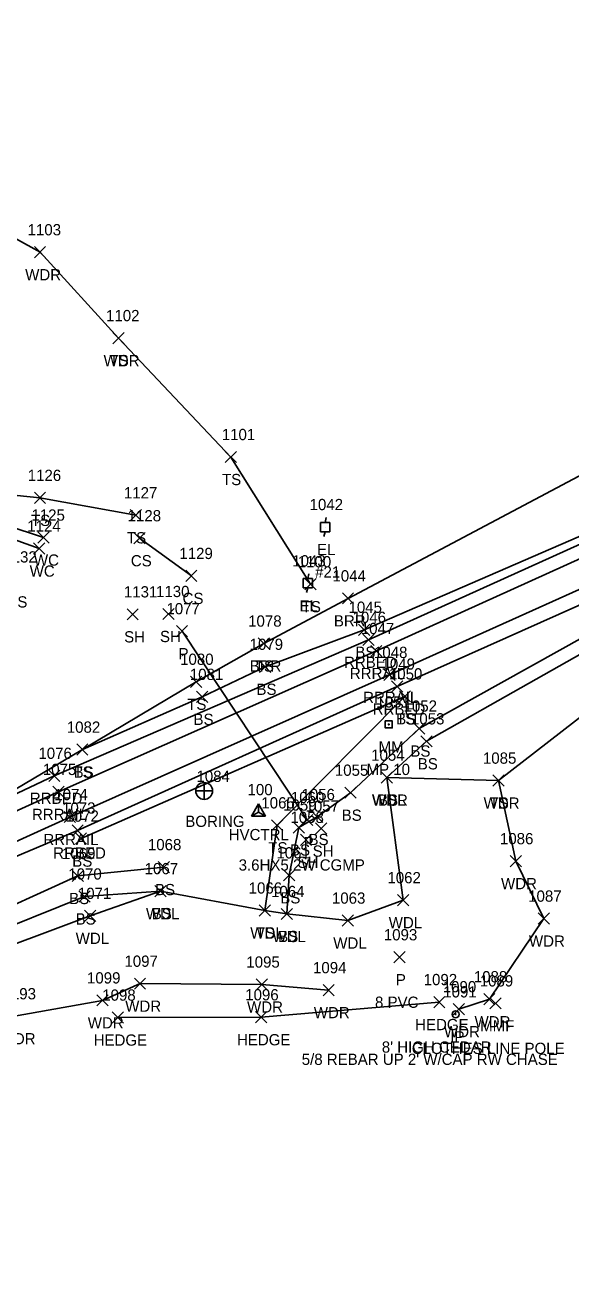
# Model space of a CAD drawing. Extents: x 1640777 to 1641692, y 610911 to 611377.
# Drawn here: x 1641419.5 to 1641516.6, y 611149.3 to 611372 of the extents above; entities that cross this region are included whole.
import ezdxf

# ---------------------------------------------------------------- set-up
doc = ezdxf.new("R2010")
doc.units = 0
for name, color, linetype in [('C_A', 7, 'Continuous'), ('C_I', 7, 'Continuous'), ('CPSM', 7, 'Continuous'), ('D_A', 7, 'Continuous'), ('D_C', 7, 'Continuous'), ('D_I', 7, 'Continuous'), ('D_TIC', 7, 'Continuous'), ('DCP', 7, 'Continuous'), ('G_A', 7, 'Continuous'), ('G_I', 7, 'Continuous'), ('GA_P', 7, 'Continuous'), ('L_A', 7, 'Continuous'), ('L_C', 7, 'Continuous'), ('L_I', 7, 'Continuous'), ('L_TIC', 7, 'Continuous'), ('LABL', 7, 'Continuous'), ('LAHR', 7, 'Continuous'), ('LAWA', 7, 'Continuous'), ('LAWE', 7, 'Continuous'), ('LELB', 7, 'Continuous'), ('M_A', 7, 'Continuous'), ('M_C', 7, 'Continuous'), ('M_I', 7, 'Continuous'), ('MPIR', 7, 'Continuous'), ('R_A', 7, 'Continuous'), ('R_I', 7, 'Continuous'), ('R_TIC', 7, 'Continuous'), ('RR', 7, 'Continuous'), ('RRB', 7, 'Continuous'), ('S_A', 7, 'Continuous'), ('S_C', 7, 'Continuous'), ('S_I', 7, 'Continuous'), ('SRM', 7, 'Continuous'), ('U_A', 7, 'Continuous'), ('U_C', 7, 'Continuous'), ('U_I', 7, 'Continuous'), ('UEPT', 7, 'Continuous')]:
    doc.layers.add(name, color=color, linetype=linetype)

msp = doc.modelspace()

# ---------------------------------------------------------------- linework, layer by layer
at = {"layer": 'CPSM'}
for p, q in [((1641459.75, 611231.37), (1641461, 611233.54)), ((1641459.75, 611231.37), (1641461, 611232.09)), ((1641462.25, 611231.37), (1641461, 611233.54)), ((1641461, 611232.09), (1641461, 611233.54)), ((1641461, 611232.09), (1641461, 611232.09)), ((1641461, 611232.09), (1641462.25, 611231.37)), ((1641459.75, 611231.37), (1641462.25, 611231.37))]:
    msp.add_line(p, q, dxfattribs=at)
at = {"layer": 'D_TIC'}
for points in [[(1641446.39, 611263.26), (1641448.39, 611265.26)], [(1641448.39, 611263.26), (1641446.39, 611265.26)], [(1641468.66, 611229.69), (1641470.66, 611231.69)], [(1641470.66, 611229.69), (1641468.66, 611231.69)], [(1641485.05, 611205.28), (1641487.05, 611207.28)], [(1641487.05, 611205.28), (1641485.05, 611207.28)]]:
    msp.add_lwpolyline(points, dxfattribs=at)
at = {"layer": 'DCP'}
msp.add_lwpolyline([(1641469.66, 611230.69), (1641447.39, 611264.26)], dxfattribs=at)
at = {"layer": 'GA_P'}
for p, q in [((1641451.33, 611235.85), (1641451.33, 611237.35)), ((1641451.33, 611235.85), (1641449.83, 611235.85)), ((1641452.83, 611235.85), (1641451.33, 611235.85)), ((1641451.33, 611234.35), (1641451.33, 611235.85))]:
    msp.add_line(p, q, dxfattribs=at)
for start, end in [(90, 180), (0, 90), (180, 270), (270, 0)]:
    msp.add_arc((1641451.33, 611235.85), 1.5, start, end, dxfattribs=at)
at = {"layer": 'L_TIC'}
for points in [[(1641421.14, 611330.65), (1641423.14, 611332.65)], [(1641423.14, 611330.65), (1641421.14, 611332.65)], [(1641435.08, 611315.38), (1641437.08, 611317.38)], [(1641437.08, 611315.38), (1641435.08, 611317.38)], [(1641435.08, 611315.38), (1641437.08, 611317.38)], [(1641437.08, 611315.38), (1641435.08, 611317.38)], [(1641455.09, 611294.23), (1641457.09, 611296.23)], [(1641457.09, 611294.23), (1641455.09, 611296.23)], [(1641421.13, 611286.97), (1641423.13, 611288.97)], [(1641423.13, 611286.97), (1641421.13, 611288.97)], [(1641438.17, 611283.87), (1641440.17, 611285.87)], [(1641440.17, 611283.87), (1641438.17, 611285.87)], [(1641421.74, 611279.91), (1641423.74, 611281.91)], [(1641423.74, 611279.91), (1641421.74, 611281.91)], [(1641438.85, 611279.79), (1641440.85, 611281.79)], [(1641440.85, 611279.79), (1641438.85, 611281.79)], [(1641420.99, 611277.95), (1641422.99, 611279.95)], [(1641422.99, 611277.95), (1641420.99, 611279.95)], [(1641448.05, 611273.09), (1641450.05, 611275.09)], [(1641450.05, 611273.09), (1641448.05, 611275.09)], [(1641469.26, 611271.61), (1641471.26, 611273.61)], [(1641471.26, 611271.61), (1641469.26, 611273.61)], [(1641475.91, 611269.1), (1641477.91, 611271.1)], [(1641477.91, 611269.1), (1641475.91, 611271.1)], [(1641437.61, 611266.26), (1641439.61, 611268.26)], [(1641439.61, 611266.26), (1641437.61, 611268.26)], [(1641443.98, 611266.32), (1641445.98, 611268.32)], [(1641445.98, 611266.32), (1641443.98, 611268.32)], [(1641478.77, 611263.52), (1641480.77, 611265.52)], [(1641480.77, 611263.52), (1641478.77, 611265.52)], [(1641460.92, 611261.06), (1641462.92, 611263.06)], [(1641462.92, 611261.06), (1641460.92, 611263.06)], [(1641460.92, 611261.06), (1641462.92, 611263.06)], [(1641462.92, 611261.06), (1641460.92, 611263.06)], [(1641461.19, 611256.93), (1641463.19, 611258.93)], [(1641463.19, 611256.93), (1641461.19, 611258.93)], [(1641448.9, 611254.27), (1641450.9, 611256.27)], [(1641450.9, 611254.27), (1641448.9, 611256.27)], [(1641449.98, 611251.58), (1641451.98, 611253.58)], [(1641451.98, 611251.58), (1641449.98, 611253.58)], [(1641486.04, 611251.67), (1641488.04, 611253.67)], [(1641488.04, 611251.67), (1641486.04, 611253.67)], [(1641486.04, 611251.67), (1641488.04, 611253.67)], [(1641488.04, 611251.67), (1641486.04, 611253.67)], [(1641488.56, 611245.95), (1641490.56, 611247.95)], [(1641490.56, 611245.95), (1641488.56, 611247.95)], [(1641489.88, 611243.68), (1641491.88, 611245.68)], [(1641491.88, 611243.68), (1641489.88, 611245.68)], [(1641428.67, 611242.2), (1641430.67, 611244.2)], [(1641430.67, 611242.2), (1641428.67, 611244.2)], [(1641428.67, 611242.2), (1641430.67, 611244.2)], [(1641430.67, 611242.2), (1641428.67, 611244.2)], [(1641482.8, 611237.22), (1641484.8, 611239.22)], [(1641484.8, 611237.22), (1641482.8, 611239.22)], [(1641482.8, 611237.22), (1641484.8, 611239.22)], [(1641484.8, 611237.22), (1641482.8, 611239.22)], [(1641482.8, 611237.22), (1641484.8, 611239.22)], [(1641484.8, 611237.22), (1641482.8, 611239.22)], [(1641502.67, 611236.69), (1641504.67, 611238.69)], [(1641504.67, 611236.69), (1641502.67, 611238.69)], [(1641502.67, 611236.69), (1641504.67, 611238.69)], [(1641504.67, 611236.69), (1641502.67, 611238.69)], [(1641476.34, 611234.54), (1641478.34, 611236.54)], [(1641478.34, 611234.54), (1641476.34, 611236.54)], [(1641470.45, 611230.22), (1641472.45, 611232.22)], [(1641472.45, 611230.22), (1641470.45, 611232.22)], [(1641463.32, 611228.74), (1641465.32, 611230.74)], [(1641465.32, 611228.74), (1641463.32, 611230.74)], [(1641467.15, 611228.35), (1641469.15, 611230.35)], [(1641469.15, 611228.35), (1641467.15, 611230.35)], [(1641471.13, 611228.16), (1641473.13, 611230.16)], [(1641473.13, 611228.16), (1641471.13, 611230.16)], [(1641428.43, 611226.38), (1641430.43, 611228.38)], [(1641430.43, 611226.38), (1641428.43, 611228.38)], [(1641468.44, 611226.16), (1641470.44, 611228.16)], [(1641470.44, 611226.16), (1641468.44, 611228.16)], [(1641443.14, 611221.31), (1641445.14, 611223.31)], [(1641445.14, 611221.31), (1641443.14, 611223.31)], [(1641505.76, 611222.37), (1641507.76, 611224.37)], [(1641507.76, 611222.37), (1641505.76, 611224.37)], [(1641427.88, 611219.73), (1641429.88, 611221.73)], [(1641429.88, 611219.73), (1641427.88, 611221.73)], [(1641465.43, 611219.85), (1641467.43, 611221.85)], [(1641467.43, 611219.85), (1641465.43, 611221.85)], [(1641429.03, 611216.09), (1641431.03, 611218.09)], [(1641431.03, 611216.09), (1641429.03, 611218.09)], [(1641442.56, 611217.04), (1641444.56, 611219.04)], [(1641444.56, 611217.04), (1641442.56, 611219.04)], [(1641442.56, 611217.04), (1641444.56, 611219.04)], [(1641444.56, 611217.04), (1641442.56, 611219.04)], [(1641485.73, 611215.43), (1641487.73, 611217.43)], [(1641487.73, 611215.43), (1641485.73, 611217.43)], [(1641430.06, 611212.64), (1641432.06, 611214.64)], [(1641432.06, 611212.64), (1641430.06, 611214.64)], [(1641461.11, 611213.6), (1641463.11, 611215.6)], [(1641463.11, 611213.6), (1641461.11, 611215.6)], [(1641461.11, 611213.6), (1641463.11, 611215.6)], [(1641463.11, 611213.6), (1641461.11, 611215.6)], [(1641465.05, 611212.97), (1641467.05, 611214.97)], [(1641467.05, 611212.97), (1641465.05, 611214.97)], [(1641465.05, 611212.97), (1641467.05, 611214.97)], [(1641467.05, 611212.97), (1641465.05, 611214.97)], [(1641475.87, 611211.8), (1641477.87, 611213.8)], [(1641477.87, 611211.8), (1641475.87, 611213.8)], [(1641510.72, 611212.15), (1641512.72, 611214.15)], [(1641512.72, 611212.15), (1641510.72, 611214.15)], [(1641438.92, 611200.58), (1641440.92, 611202.58)], [(1641440.92, 611200.58), (1641438.92, 611202.58)], [(1641460.6, 611200.43), (1641462.6, 611202.43)], [(1641462.6, 611200.43), (1641460.6, 611202.43)], [(1641472.47, 611199.43), (1641474.47, 611201.43)], [(1641474.47, 611199.43), (1641472.47, 611201.43)], [(1641432.27, 611197.61), (1641434.27, 611199.61)], [(1641434.27, 611197.61), (1641432.27, 611199.61)], [(1641492.15, 611197.31), (1641494.15, 611199.31)], [(1641494.15, 611197.31), (1641492.15, 611199.31)], [(1641495.62, 611196.04), (1641497.62, 611198.04)], [(1641497.62, 611196.04), (1641495.62, 611198.04)], [(1641501.05, 611197.81), (1641503.05, 611199.81)], [(1641503.05, 611197.81), (1641501.05, 611199.81)], [(1641502.12, 611197.08), (1641504.12, 611199.08)], [(1641504.12, 611197.08), (1641502.12, 611199.08)], [(1641434.97, 611194.55), (1641436.97, 611196.55)], [(1641436.97, 611194.55), (1641434.97, 611196.55)], [(1641460.46, 611194.61), (1641462.46, 611196.61)], [(1641462.46, 611194.61), (1641460.46, 611196.61)]]:
    msp.add_lwpolyline(points, dxfattribs=at)
at = {"layer": 'LABL'}
msp.add_lwpolyline([(1641586.48, 611324.25), (1641557.5, 611311.65), (1641520.84, 611293.34), (1641476.91, 611270.1), (1641461.92, 611262.06)], dxfattribs=at)
at = {"layer": 'LAHR'}
msp.add_lwpolyline([(1641493.15, 611198.31), (1641461.46, 611195.61), (1641435.97, 611195.55)], dxfattribs=at)
at = {"layer": 'LAWA'}
for points in [[(1641436.08, 611316.38), (1641422.14, 611331.65), (1641394.71, 611346.86), (1641371.98, 611360.67), (1641343.92, 611372.04)], [(1641483.8, 611238.22), (1641486.73, 611216.43), (1641476.87, 611212.8), (1641466.05, 611213.97), (1641462.11, 611214.6), (1641443.56, 611218.04), (1641431.06, 611213.64), (1641409.03, 611205.4), (1641402.82, 611195.65), (1641388.13, 611189.58), (1641355.81, 611176.64), (1641324.2, 611160.29), (1641294.38, 611149.25)], [(1641483.8, 611238.22), (1641503.67, 611237.69), (1641506.76, 611223.37), (1641511.72, 611213.15), (1641502.05, 611198.81), (1641496.62, 611197.04)], [(1641473.47, 611200.43), (1641461.6, 611201.43), (1641439.92, 611201.58), (1641433.27, 611198.61), (1641417.6, 611195.79), (1641410.59, 611179.12), (1641389.69, 611159.78)]]:
    msp.add_lwpolyline(points, dxfattribs=at)
at = {"layer": 'LAWE'}
for points in [[(1641324.03, 611338.78), (1641353.31, 611314.49), (1641379.55, 611298.51), (1641407.41, 611284.19), (1641421.99, 611278.95)], [(1641326.81, 611339.67), (1641353.07, 611317.43), (1641379.77, 611302.03), (1641409.24, 611285.37), (1641422.74, 611280.91)]]:
    msp.add_lwpolyline(points, dxfattribs=at)
at = {"layer": 'LELB'}
for points in [[(1641327.03, 611340.88), (1641353.94, 611320.79), (1641381.19, 611305.37), (1641411.65, 611289.02), (1641422.13, 611287.97), (1641439.17, 611284.87)], [(1641587.44, 611330.19), (1641595.78, 611321.25), (1641559.33, 611304.47), (1641524.18, 611283.76), (1641479.77, 611264.52), (1641462.19, 611257.93), (1641450.98, 611252.58), (1641429.67, 611243.2)], [(1641470.26, 611272.61), (1641456.09, 611295.23), (1641436.08, 611316.38)], [(1641633.9, 611290.45), (1641608.26, 611307.49), (1641568.47, 611290.94), (1641529.14, 611269), (1641489.56, 611246.95), (1641477.34, 611235.54), (1641471.45, 611231.22), (1641468.15, 611229.35), (1641466.43, 611220.85), (1641466.05, 611213.97)], [(1641631.08, 611287.49), (1641606.47, 611297.59), (1641570.47, 611285.32), (1641529.85, 611266.73), (1641490.88, 611244.68), (1641483.8, 611238.22)], [(1641626.63, 611284.15), (1641608.25, 611289.29), (1641573.95, 611281.99), (1641532.9, 611260.34), (1641503.67, 611237.69)], [(1641439.85, 611280.79), (1641449.05, 611274.09)], [(1641461.92, 611262.06), (1641449.9, 611255.27), (1641429.67, 611243.2), (1641410.57, 611231.91)], [(1641487.04, 611252.67), (1641429.43, 611227.38)], [(1641487.04, 611252.67), (1641464.32, 611229.74), (1641462.11, 611214.6)], [(1641444.14, 611222.31), (1641428.88, 611220.73), (1641409.53, 611211.97), (1641379.62, 611198.46), (1641351.15, 611186.99), (1641317.17, 611171.97), (1641288.28, 611159.79)], [(1641443.56, 611218.04), (1641430.03, 611217.09), (1641411.42, 611209.64), (1641380.75, 611196.66), (1641351.81, 611184.71), (1641318.07, 611170.34), (1641289.05, 611157.6)]]:
    msp.add_lwpolyline(points, dxfattribs=at)
at = {"layer": 'MPIR'}
for radius in [0.625, 0.0833]:
    msp.add_circle((1641496.05, 611196.13), radius, dxfattribs=at)
at = {"layer": 'R_TIC'}
for points in [[(1641479.55, 611261.73), (1641481.55, 611263.73)], [(1641481.55, 611261.73), (1641479.55, 611263.73)], [(1641480.95, 611259.74), (1641482.95, 611261.74)], [(1641482.95, 611259.74), (1641480.95, 611261.74)], [(1641483.31, 611255.48), (1641485.31, 611257.48)], [(1641485.31, 611255.48), (1641483.31, 611257.48)], [(1641484.65, 611253.42), (1641486.65, 611255.42)], [(1641486.65, 611253.42), (1641484.65, 611255.42)], [(1641423.68, 611237.55), (1641425.68, 611239.55)], [(1641425.68, 611237.55), (1641423.68, 611239.55)], [(1641424.41, 611234.68), (1641426.41, 611236.68)], [(1641426.41, 611234.68), (1641424.41, 611236.68)], [(1641426.45, 611230.21), (1641428.45, 611232.21)], [(1641428.45, 611230.21), (1641426.45, 611232.21)], [(1641427.83, 611227.82), (1641429.83, 611229.82)], [(1641429.83, 611227.82), (1641427.83, 611229.82)]]:
    msp.add_lwpolyline(points, dxfattribs=at)
at = {"layer": 'RR'}
for points in [[(1641609.96, 611319.36), (1641563.93, 611298), (1641524.67, 611280.09), (1641481.95, 611260.74), (1641425.41, 611235.68), (1641374.39, 611212.53), (1641348.91, 611200.83), (1641315.51, 611185.65), (1641281.43, 611170.17)], [(1641614.1, 611315.75), (1641566.38, 611293.79), (1641526.34, 611275.4), (1641484.31, 611256.48), (1641427.45, 611231.21), (1641376.17, 611207.95), (1641351.03, 611196.44), (1641317.13, 611181.1), (1641283.87, 611165.86)]]:
    msp.add_lwpolyline(points, dxfattribs=at)
at = {"layer": 'RRB'}
for points in [[(1641601.06, 611318.54), (1641562.35, 611300.7), (1641524.48, 611282.6), (1641480.55, 611262.73), (1641424.68, 611238.55), (1641410.57, 611231.91), (1641373.51, 611214.53), (1641347.89, 611203.18), (1641314.84, 611187.71), (1641280.56, 611172.25)], [(1641612.04, 611311.61), (1641567.84, 611291.83), (1641527.22, 611272.95), (1641485.65, 611254.42), (1641428.83, 611228.82), (1641404.18, 611218.43), (1641376.76, 611205.98), (1641350.39, 611191.7), (1641314.2, 611175.58), (1641286.94, 611162.71)]]:
    msp.add_lwpolyline(points, dxfattribs=at)
at = {"layer": 'SRM'}
msp.add_lwpolyline([(1641483.53, 611248.31), (1641484.78, 611248.31), (1641484.78, 611247.06), (1641483.53, 611247.06)], close=True, dxfattribs=at)
msp.add_circle((1641484.16, 611247.68), 0.0833, dxfattribs=at)
at = {"layer": 'UEPT'}
for p, q in [((1641472.02, 611281.95), (1641472.02, 611283.61)), ((1641472.02, 611283.61), (1641473.69, 611283.61)), ((1641473.02, 611284.45), (1641472.85, 611283.61)), ((1641472.85, 611282.78), (1641472.85, 611282.78)), ((1641473.69, 611283.61), (1641473.69, 611281.95)), ((1641473.69, 611281.95), (1641472.02, 611281.95)), ((1641472.6, 611281.11), (1641472.85, 611281.95)), ((1641469.92, 611274.44), (1641469.76, 611273.61)), ((1641468.92, 611271.94), (1641468.92, 611273.61)), ((1641468.92, 611273.61), (1641470.59, 611273.61)), ((1641470.59, 611271.94), (1641468.92, 611271.94)), ((1641469.51, 611271.11), (1641469.76, 611271.94)), ((1641469.76, 611272.77), (1641469.76, 611272.77)), ((1641470.59, 611273.61), (1641470.59, 611271.94))]:
    msp.add_line(p, q, dxfattribs=at)

# ---------------------------------------------------------------- texts
at = {"layer": 'C_A'}
msp.add_text('HVCTRL', height=2, dxfattribs=at).set_placement((1641455.69, 611227.09))
at = {"layer": 'C_I'}
msp.add_text('100', height=2, dxfattribs=at).set_placement((1641459.04, 611235.09))
at = {"layer": 'D_A'}
for p in [(1641446.77, 611259.26), (1641469.03, 611225.69), (1641485.42, 611201.28)]:
    msp.add_text('P', height=2, dxfattribs=at).set_placement(p)
at = {"layer": 'D_C'}
for s, p in [('3.6HX5.2W CGMP', (1641457.46, 611221.69)), ('8 PVC', (1641481.71, 611197.28))]:
    msp.add_text(s, height=2, dxfattribs=at).set_placement(p)
at = {"layer": 'D_I'}
for s, p in [('1077', (1641444.62, 611267.26)), ('1060', (1641466.75, 611233.69)), ('1093', (1641483.28, 611209.28))]:
    msp.add_text(s, height=2, dxfattribs=at).set_placement(p)
at = {"layer": 'G_A'}
msp.add_text('BORING', height=2, dxfattribs=at).set_placement((1641447.97, 611229.45))
at = {"layer": 'G_I'}
msp.add_text('1084', height=2, dxfattribs=at).set_placement((1641449.96, 611237.45))
at = {"layer": 'L_A'}
for s, p in [('WDR', (1641419.5, 611326.65)), ('WDR', (1641433.44, 611311.38)), ('TS', (1641434.49, 611311.38)), ('TS', (1641454.5, 611290.23)), ('TS', (1641420.54, 611282.97)), ('TS', (1641437.58, 611279.87)), ('WC', (1641420.3, 611273.95)), ('WC', (1641421.05, 611275.91)), ('CS', (1641438.29, 611275.79)), ('CS', (1641416.18, 611268.47)), ('CS', (1641447.49, 611269.09)), ('TS', (1641468.67, 611267.61)), ('BRR', (1641474.4, 611265.1)), ('SH', (1641437.1, 611262.26)), ('SH', (1641443.47, 611262.32)), ('BS', (1641478.21, 611259.52)), ('BRR', (1641459.41, 611257.06)), ('TS', (1641460.33, 611257.06)), ('BS', (1641460.63, 611252.93)), ('TS', (1641448.31, 611250.27)), ('BS', (1641449.43, 611247.58)), ('TS', (1641485.45, 611247.67)), ('BS', (1641485.48, 611247.67)), ('BS', (1641488, 611241.95)), ('BS', (1641489.32, 611239.68)), ('TS', (1641428.08, 611238.2)), ('BS', (1641428.11, 611238.2)), ('WDR', (1641481.16, 611233.22)), ('WDL', (1641481.22, 611233.22)), ('BS', (1641482.24, 611233.22)), ('WDR', (1641501.03, 611232.69)), ('TS', (1641502.08, 611232.69)), ('BS', (1641475.78, 611230.54)), ('BS', (1641469.89, 611226.22)), ('TS', (1641462.73, 611224.74)), ('BS', (1641466.59, 611224.35)), ('SH', (1641470.62, 611224.16)), ('BS', (1641427.87, 611222.38)), ('SH', (1641467.93, 611222.16)), ('WDR', (1641504.12, 611218.37)), ('BS', (1641442.58, 611217.31)), ('BS', (1641427.32, 611215.73)), ('BS', (1641464.87, 611215.85)), ('BS', (1641428.47, 611212.09)), ('WDL', (1641440.98, 611213.04)), ('BS', (1641442.01, 611213.04)), ('WDL', (1641459.53, 611209.6)), ('TS', (1641460.52, 611209.6)), ('WDL', (1641484.15, 611211.43)), ('WDL', (1641428.48, 611208.64)), ('WDL', (1641463.47, 611208.97)), ('BS', (1641464.49, 611208.97)), ('WDL', (1641474.29, 611207.8)), ('WDR', (1641509.09, 611208.15)), ('WDR', (1641437.29, 611196.58)), ('WDR', (1641458.96, 611196.43)), ('WDR', (1641470.83, 611195.43)), ('WDR', (1641499.41, 611193.81)), ('WDR', (1641430.63, 611193.61)), ('HEDGE', (1641488.85, 611193.31)), ('WDR', (1641493.98, 611192.04)), ('MMF', (1641500.41, 611193.08)), ('WDR', (1641414.96, 611190.79)), ('HEDGE', (1641431.67, 611190.55)), ('HEDGE', (1641457.16, 611190.61))]:
    msp.add_text(s, height=2, dxfattribs=at).set_placement(p)
at = {"layer": 'L_C'}
for s, p in [("8' HIGH CEDAR", (1641482.92, 611189.31)), ('CLOTHES LINE POLE', (1641488.24, 611189.08))]:
    msp.add_text(s, height=2, dxfattribs=at).set_placement(p)
at = {"layer": 'L_I'}
for s, p in [('1103', (1641419.93, 611334.65)), ('1102', (1641433.88, 611319.38)), ('1102', (1641433.88, 611319.38)), ('1101', (1641454.46, 611298.23)), ('1126', (1641419.95, 611290.97)), ('1127', (1641437.05, 611287.87)), ('1125', (1641420.61, 611283.91)), ('1128', (1641437.72, 611283.79)), ('1124', (1641419.86, 611281.95)), ('1132', (1641415.61, 611276.47)), ('1132', (1641415.61, 611276.47)), ('1129', (1641446.92, 611277.09)), ('1100', (1641467.97, 611275.61)), ('1044', (1641474.14, 611273.1)), ('1131', (1641437.05, 611270.26)), ('1130', (1641442.77, 611270.32)), ('1045', (1641477, 611267.52)), ('1078', (1641459.15, 611265.06)), ('1078', (1641459.15, 611265.06)), ('1079', (1641459.41, 611260.93)), ('1080', (1641447.05, 611258.27)), ('1081', (1641448.78, 611255.58)), ('1050', (1641484.18, 611255.67)), ('1050', (1641484.18, 611255.67)), ('1052', (1641486.79, 611249.95)), ('1053', (1641488.11, 611247.68)), ('1082', (1641426.9, 611246.2)), ('1082', (1641426.9, 611246.2)), ('1054', (1641481.03, 611241.22)), ('1054', (1641481.03, 611241.22)), ('1054', (1641481.03, 611241.22)), ('1085', (1641500.9, 611240.69)), ('1085', (1641500.9, 611240.69)), ('1055', (1641474.57, 611238.54)), ('1056', (1641468.63, 611234.22)), ('1065', (1641461.5, 611232.74)), ('1059', (1641465.37, 611232.35)), ('1057', (1641469.36, 611232.16)), ('1072', (1641426.65, 611230.38)), ('1058', (1641466.67, 611230.16)), ('1068', (1641441.32, 611225.31)), ('1086', (1641503.93, 611226.37)), ('1069', (1641426.05, 611223.73)), ('1061', (1641464.18, 611223.85)), ('1067', (1641440.75, 611221.04)), ('1067', (1641440.75, 611221.04)), ('1070', (1641427.17, 611220.09)), ('1062', (1641483.92, 611219.43)), ('1071', (1641428.86, 611216.64)), ('1066', (1641459.24, 611217.6)), ('1066', (1641459.24, 611217.6)), ('1064', (1641463.23, 611216.97)), ('1064', (1641463.23, 611216.97)), ('1087', (1641508.95, 611216.15)), ('1063', (1641474.05, 611215.8)), ('1097', (1641437.15, 611204.58)), ('1095', (1641458.83, 611204.43)), ('1094', (1641470.69, 611203.43)), ('1099', (1641430.49, 611201.61)), ('1092', (1641490.37, 611201.31)), ('1088', (1641499.28, 611201.81)), ('1089', (1641500.34, 611201.08)), ('1193', (1641415.47, 611198.79)), ('1098', (1641433.2, 611198.55)), ('1096', (1641458.63, 611198.61)), ('1090', (1641493.76, 611200.04))]:
    msp.add_text(s, height=2, dxfattribs=at).set_placement(p)
at = {"layer": 'M_A'}
msp.add_text('IP', height=2, dxfattribs=at).set_placement((1641495.1, 611191.13))
at = {"layer": 'M_C'}
msp.add_text("5/8 REBAR UP 2' W/CAP RW CHASE", height=2, dxfattribs=at).set_placement((1641468.68, 611187.13))
at = {"layer": 'M_I'}
msp.add_text('1091', height=2, dxfattribs=at).set_placement((1641493.85, 611199.13))
at = {"layer": 'R_A'}
for s, p in [('RRBED', (1641476.2, 611257.73)), ('RRRAIL', (1641477.24, 611255.74)), ('RRRAIL', (1641479.6, 611251.48)), ('RRBED', (1641481.3, 611249.42)), ('RRBED', (1641420.33, 611233.55)), ('RRRAIL', (1641420.7, 611230.68)), ('RRRAIL', (1641422.74, 611226.21)), ('RRBED', (1641424.48, 611223.82))]:
    msp.add_text(s, height=2, dxfattribs=at).set_placement(p)
at = {"layer": 'R_I'}
for s, p in [('1046', (1641477.72, 611265.73)), ('1047', (1641479.18, 611263.74)), ('1048', (1641481.53, 611259.48)), ('1049', (1641482.87, 611257.42)), ('1076', (1641421.85, 611241.55)), ('1075', (1641422.64, 611238.68)), ('1074', (1641424.68, 611234.21)), ('1073', (1641426.06, 611231.82))]:
    msp.add_text(s, height=2, dxfattribs=at).set_placement(p)
at = {"layer": 'S_A'}
msp.add_text('MM', height=2, dxfattribs=at).set_placement((1641482.35, 611242.68))
at = {"layer": 'S_C'}
msp.add_text('MP 10', height=2, dxfattribs=at).set_placement((1641480.21, 611238.68))
at = {"layer": 'S_I'}
msp.add_text('1051', height=2, dxfattribs=at).set_placement((1641481.95, 611250.68))
at = {"layer": 'U_A'}
for p in [(1641471.39, 611277.78), (1641468.29, 611267.77)]:
    msp.add_text('EL', height=2, dxfattribs=at).set_placement(p)
at = {"layer": 'U_C'}
msp.add_text('#21', height=2, dxfattribs=at).set_placement((1641471.06, 611273.78))
at = {"layer": 'U_I'}
for s, p in [('1042', (1641470.08, 611285.78)), ('1043', (1641466.99, 611275.77))]:
    msp.add_text(s, height=2, dxfattribs=at).set_placement(p)

doc.saveas('drawing.dxf')
